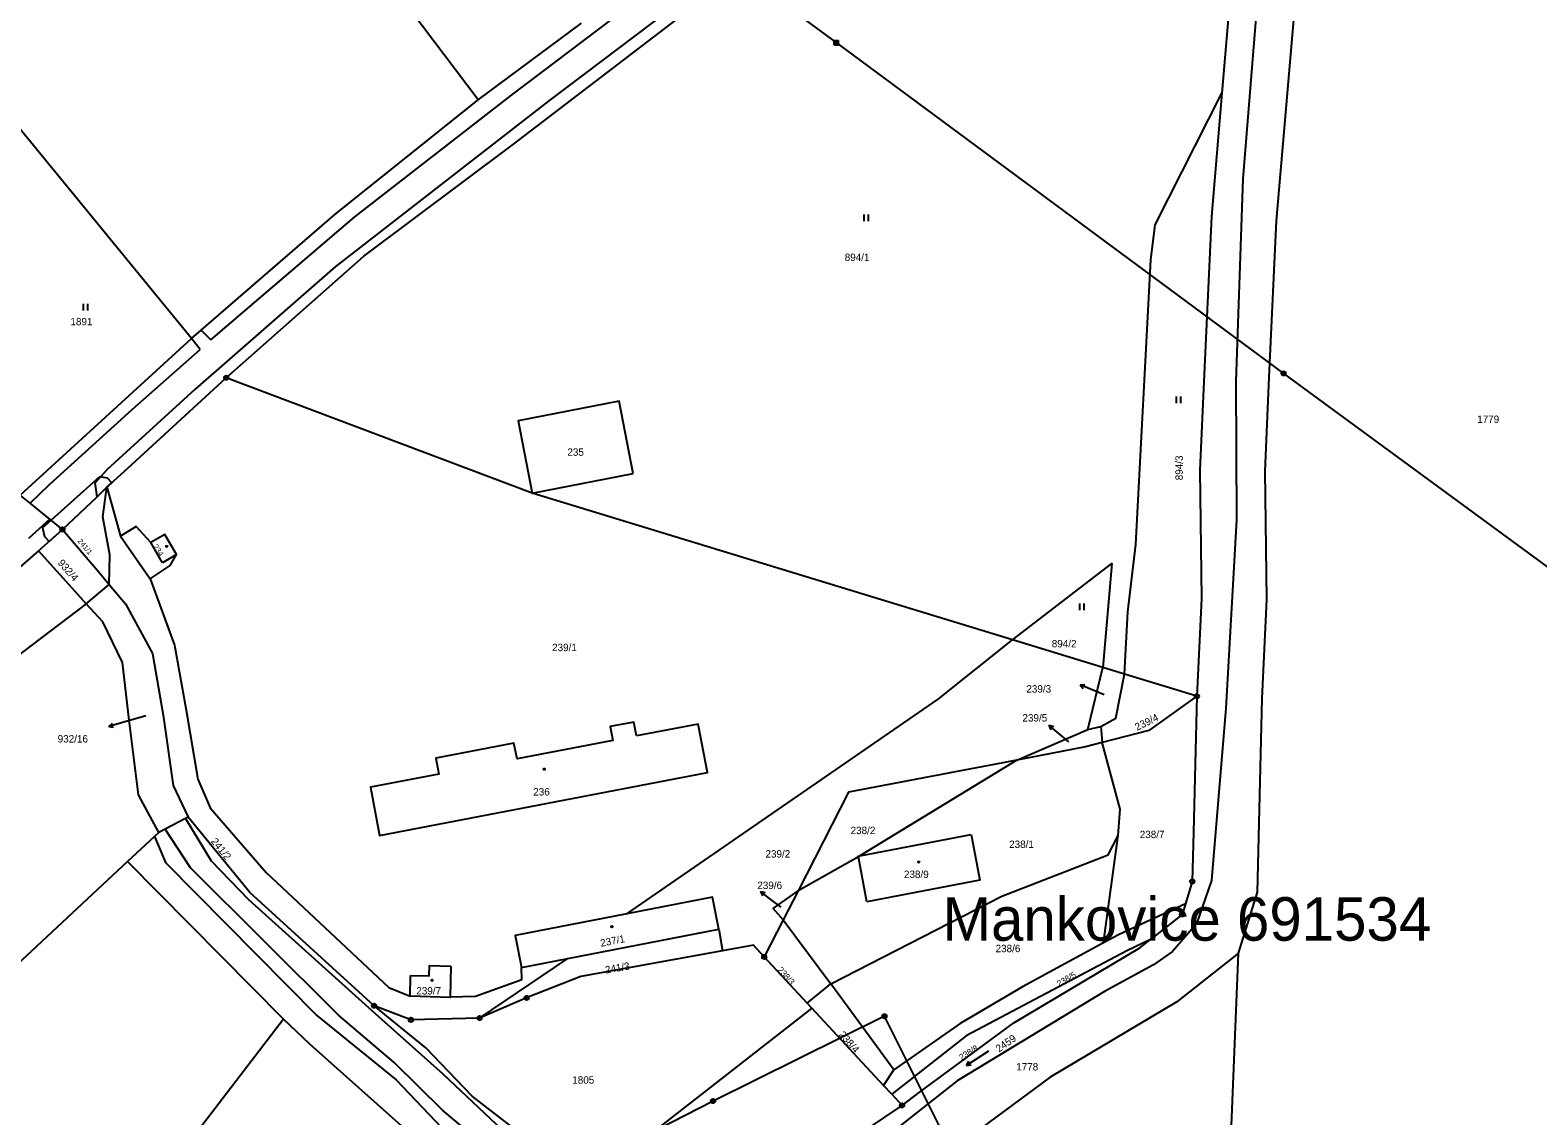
# Model space of a CAD drawing. Extents: x -504988 to -494607, y -1123820 to -1114018.
# Drawn here: x -501232.9 to -500886.6, y -1120834.1 to -1120584.6 of the extents above; entities that cross this region are included whole.
import ezdxf

# ---------------------------------------------------------------- set-up
doc = ezdxf.new("R2010")
doc.units = 0
for name, color, linetype in [('Hranice parcel', 7, 'Continuous'), ('Parcelní čísla', 7, 'Continuous'), ('Pop  PČ popisy', 7, 'Continuous'), ('Poz předměty', 7, 'Continuous'), ('Vnitřní kresba', 7, 'Continuous'), ('Věcná břemena k části', 7, 'Continuous'), ('Značky bodu BP', 7, 'Continuous'), ('Značky budov', 7, 'Continuous'), ('Značky kultur', 7, 'Continuous')]:
    doc.layers.add(name, color=color, linetype=linetype)

msp = doc.modelspace()

# ---------------------------------------------------------------- linework, layer by layer
at = {"layer": 'Hranice parcel'}
for p, q in [((-501130, -1120600.61), (-501186.29, -1120526.21)), ((-501130, -1120600.61), (-501106.28, -1120583.04)), ((-501235.2, -1120691.45), (-501195.89, -1120655.5)), ((-501215.28, -1120689.67), (-501212.14, -1120700.88)), ((-501230.98, -1120704.27), (-501225.49, -1120699.35)), ((-501212.14, -1120700.88), (-501205.36, -1120710.72)), ((-501220.02, -1120716.41), (-501214.75, -1120712.02)), ((-501220.02, -1120716.41), (-501366.55, -1120827.4)), ((-500986.5, -1120731.07), (-501007.24, -1120724.73)), ((-500989.97, -1120745.29), (-500986.5, -1120731.07)), ((-500981.55, -1120732.58), (-500986.5, -1120731.07)), ((-500964.91, -1120737.67), (-500981.55, -1120732.58)), ((-500989.97, -1120745.29), (-500986.94, -1120744.63)), ((-500986.94, -1120744.63), (-500986.67, -1120748.33)), ((-501006.25, -1120752.34), (-500989.97, -1120745.29)), ((-501006.25, -1120752.34), (-501042.29, -1120774.34)), ((-501196.61, -1120765.46), (-501197.25, -1120765.8)), ((-501203.37, -1120768.99), (-501204.37, -1120769.92)), ((-501201.9, -1120768.22), (-501203.37, -1120768.99)), ((-501197.25, -1120765.8), (-501201.9, -1120768.22)), ((-501204.37, -1120769.92), (-501210.52, -1120775.64)), ((-501042.29, -1120774.34), (-501016.74, -1120769.45)), ((-500986.36, -1120794.35), (-500983, -1120769.64)), ((-501210.52, -1120775.64), (-501314.36, -1120872.14)), ((-501174.71, -1120811.84), (-501210.52, -1120775.64)), ((-501042.67, -1120774.56), (-501056.51, -1120782.35)), ((-501040.7, -1120784.89), (-501042.67, -1120774.56)), ((-501056.51, -1120782.35), (-501059.92, -1120789.02)), ((-501059.92, -1120789.02), (-501064.3, -1120797.57)), ((-501059.92, -1120789.02), (-501049, -1120803.74)), ((-501109.41, -1120797.95), (-501074.74, -1120791.19)), ((-501074.74, -1120791.19), (-501073.87, -1120796.18)), ((-500959.49, -1120899.46), (-500955.35, -1120796.7)), ((-501136.26, -1120799.7), (-501136.44, -1120806.74)), ((-501129.67, -1120811.62), (-501109.41, -1120797.95)), ((-501120.03, -1120800.02), (-501109.41, -1120797.95)), ((-501054.46, -1120808.17), (-501064.3, -1120797.57)), ((-501145.66, -1120806.61), (-501145.55, -1120801.81)), ((-501054.46, -1120808.17), (-501049, -1120803.74)), ((-501034.53, -1120823.54), (-501049, -1120803.74)), ((-501053.37, -1120809.34), (-501105.86, -1120850.26)), ((-501053.37, -1120809.34), (-501054.46, -1120808.17)), ((-501036.9, -1120827.08), (-501053.37, -1120809.34)), ((-501174.71, -1120811.84), (-501240.43, -1120897.51)), ((-501036.9, -1120827.08), (-501034.53, -1120823.54)), ((-501035, -1120829.12), (-501036.9, -1120827.08)), ((-501035, -1120829.12), (-501032.63, -1120831.67))]:
    msp.add_line(p, q, dxfattribs=at)
for points in [[(-500953.35, -1120500.48), (-500952.09, -1120504.18), (-500951.44, -1120512.93), (-500952.93, -1120529.76), (-500954.82, -1120550.96), (-500957.14, -1120574.84), (-500959.18, -1120599.12)], [(-500947.89, -1120547.6), (-500950.64, -1120573.28), (-500954.32, -1120618.75), (-500955.93, -1120665.39), (-500955.81, -1120697.13), (-500958.29, -1120740.41), (-500961.53, -1120780.04), (-500965, -1120789.98), (-500970.48, -1120796.33), (-500974.88, -1120799.38), (-500986.12, -1120805.48), (-501019.95, -1120826.04), (-501047.16, -1120847.46), (-501062.53, -1120859.4), (-501071.7, -1120870.74), (-501073.06, -1120874.33), (-501072.36, -1120882.36)], [(-500955.35, -1120796.7), (-500951.01, -1120782.68), (-500949.92, -1120738.22), (-500948.81, -1120715.48), (-500949.25, -1120685.97), (-500948.28, -1120664.36), (-500946.58, -1120628.41), (-500941.57, -1120569.67), (-500939.6, -1120548.48)], [(-501187.87, -1120664.49), (-501156.29, -1120636.52), (-501121.86, -1120610.86), (-501053.65, -1120558.6), (-501052.27, -1120557.56), (-501048.06, -1120554.37)], [(-501195.89, -1120655.5), (-501252.94, -1120585.81), (-501254.29, -1120586.94)], [(-500981.55, -1120732.58), (-500980.8, -1120718.25), (-500978.95, -1120702.84), (-500975.46, -1120637.37), (-500974.45, -1120629.33), (-500959.18, -1120599.12)], [(-500959.18, -1120599.12), (-500961.55, -1120627.43), (-500963.26, -1120663.67), (-500964.26, -1120685.74), (-500963.82, -1120715.23), (-500964.91, -1120737.67)], [(-501195.89, -1120655.5), (-501193.62, -1120653.54), (-501163.04, -1120627.08), (-501130, -1120600.61)], [(-501215.28, -1120689.67), (-501210.5, -1120685.27), (-501187.87, -1120664.49)], [(-501007.24, -1120724.73), (-501117.61, -1120691), (-501187.87, -1120664.49)], [(-501094.41, -1120686.47), (-501097.65, -1120669.88), (-501120.84, -1120674.41), (-501117.61, -1120691), (-501094.41, -1120686.47)], [(-501225.49, -1120699.35), (-501228.4, -1120696.98), (-501232.93, -1120693.3), (-501235.2, -1120691.45)], [(-501225.49, -1120699.35), (-501217.56, -1120691.83), (-501215.28, -1120689.67)], [(-501214.75, -1120712.02), (-501214.62, -1120705.15), (-501216.24, -1120696.42), (-501215.28, -1120689.67)], [(-501225.49, -1120699.35), (-501217.33, -1120708.97), (-501214.75, -1120712.02)], [(-501205.36, -1120710.72), (-501200.74, -1120707.63), (-501199.26, -1120705.12), (-501201.96, -1120700.48), (-501205.21, -1120702.36), (-501208.58, -1120698.66), (-501212.14, -1120700.88)], [(-501230.98, -1120704.27), (-501252.35, -1120722.85), (-501305.53, -1120771.37), (-501366.55, -1120827.4)], [(-501220.02, -1120716.41), (-501222.57, -1120713.59), (-501230.98, -1120704.27)], [(-501007.24, -1120724.73), (-500984.47, -1120707.2), (-500986.5, -1120731.07)], [(-501214.75, -1120712.02), (-501211, -1120716.45), (-501204.81, -1120727.86), (-501202.33, -1120742.03), (-501200.04, -1120758.21), (-501196.61, -1120765.46)], [(-501205.36, -1120710.72), (-501199.78, -1120725.91), (-501197.05, -1120740.84), (-501194.38, -1120756.72), (-501191.54, -1120763.33), (-501178.69, -1120778.14), (-501150.56, -1120804.61), (-501145.66, -1120806.61)], [(-501203.37, -1120768.99), (-501208.01, -1120760.34), (-501210.19, -1120743.14), (-501211.74, -1120729.94), (-501216.22, -1120720.61), (-501220.02, -1120716.41)], [(-501095.84, -1120787.63), (-501024.32, -1120738.34), (-501007.24, -1120724.73)], [(-500986.94, -1120744.63), (-500983.51, -1120742.68), (-500981.55, -1120732.58)], [(-500964.91, -1120737.67), (-500975.93, -1120745.52), (-500986.67, -1120748.33)], [(-500964.91, -1120737.67), (-500965.67, -1120768.89), (-500965.95, -1120780.23), (-500967.54, -1120785.34)], [(-501093.61, -1120746.8), (-501094.22, -1120743.61), (-501099.65, -1120744.62), (-501099.03, -1120747.84), (-501121.08, -1120752.08), (-501121.78, -1120748.45), (-501139.75, -1120751.91), (-501139.05, -1120755.54), (-501154.76, -1120758.57), (-501152.63, -1120769.66), (-501077.3, -1120755.17), (-501079.43, -1120744.07), (-501093.61, -1120746.8)], [(-500986.67, -1120748.33), (-500990.47, -1120749.33), (-501006.25, -1120752.34)], [(-500983, -1120769.64), (-500982.54, -1120763.63), (-500986.67, -1120748.33)], [(-501006.25, -1120752.34), (-501044.92, -1120759.73), (-501056.51, -1120782.35)], [(-501153.91, -1120808.77), (-501182.43, -1120782.74), (-501196.61, -1120765.46)], [(-501046.7, -1120951.7), (-501049.76, -1120930.89), (-501064.68, -1120897.65), (-501079.51, -1120883.82), (-501096.53, -1120870.39), (-501115.41, -1120851.92), (-501138.23, -1120832.75), (-501149.31, -1120821.85), (-501162.09, -1120810.95), (-501196.12, -1120777.08), (-501201.9, -1120768.22)], [(-501197.25, -1120765.8), (-501191.36, -1120775.48), (-501182.76, -1120784.36), (-501152.9, -1120811.26), (-501138.08, -1120824.43), (-501123.11, -1120838.57), (-501110.83, -1120850.18), (-501100.06, -1120859.64), (-501084.74, -1120871.11), (-501076.33, -1120879)], [(-501204.37, -1120769.92), (-501201.85, -1120775.87), (-501167.05, -1120811.05), (-501148.8, -1120825.79), (-501138.33, -1120836.82), (-501117.04, -1120855.26), (-501098.03, -1120873.19), (-501091.8, -1120877.35), (-501089.38, -1120879.29), (-501082.27, -1120886.18), (-501066.39, -1120898.56), (-501051.55, -1120929.97), (-501051.19, -1120935.29), (-501048.87, -1120953.86), (-501041.61, -1120973.69), (-501040.41, -1120978.52), (-501040.21, -1120982.32), (-501040.6, -1120985.9), (-501041.96, -1120990.46), (-501043.41, -1120993.34), (-501047.71, -1121000.62)], [(-501049, -1120803.74), (-501009.68, -1120783.6), (-500985.25, -1120774.14), (-500983, -1120769.64)], [(-501016.74, -1120769.45), (-501014.74, -1120779.94), (-501040.7, -1120784.89)], [(-501042.67, -1120774.56), (-501042.69, -1120774.41), (-501042.29, -1120774.34)], [(-501059.92, -1120789.02), (-501062.22, -1120786.47), (-501056.51, -1120782.35)], [(-501074.74, -1120791.19), (-501076.18, -1120783.8), (-501095.84, -1120787.63)], [(-500967.54, -1120785.34), (-500982.93, -1120792.48), (-500986.36, -1120794.35)], [(-500967.54, -1120785.34), (-500968.3, -1120787.81), (-500975.55, -1120793.54)], [(-501095.84, -1120787.63), (-501121.47, -1120792.63), (-501120.03, -1120800.02)], [(-501073.87, -1120796.18), (-501106.45, -1120802.06), (-501118.87, -1120806.98), (-501129.67, -1120811.62)], [(-501064.3, -1120797.57), (-501066.78, -1120794.9), (-501073.87, -1120796.18)], [(-500955.35, -1120796.7), (-500969.5, -1120807.87), (-500998.63, -1120825.2), (-501019.77, -1120840.79), (-501071.05, -1120883.47)], [(-500975.55, -1120793.54), (-500981.01, -1120796.17), (-501017.88, -1120815.67), (-501035, -1120829.12)], [(-500986.36, -1120794.35), (-501004.94, -1120804.45), (-501019.25, -1120812.85), (-501034.53, -1120823.54)], [(-501032.63, -1120831.67), (-501028.71, -1120828.74), (-501006.93, -1120812.69), (-500978.02, -1120795.49), (-500975.55, -1120793.54)], [(-501145.55, -1120801.81), (-501141.26, -1120801.93), (-501141.2, -1120799.56), (-501136.26, -1120799.7)], [(-501136.44, -1120806.74), (-501130.58, -1120806.56), (-501119.97, -1120802.75), (-501120.03, -1120800.02)], [(-501136.44, -1120806.74), (-501136.44, -1120806.9), (-501145.66, -1120806.61)], [(-501105.86, -1120850.26), (-501113.83, -1120843.12), (-501131.41, -1120829.58), (-501142, -1120818.43), (-501153.91, -1120808.77)], [(-501129.67, -1120811.62), (-501145.46, -1120812.02), (-501153.91, -1120808.77)], [(-501114.57, -1120865.85), (-501168.67, -1120817.63), (-501174.71, -1120811.84)], [(-501080.17, -1120873.27), (-501077.62, -1120868.06), (-501070.91, -1120860.89), (-501057.97, -1120850.7), (-501040.78, -1120837.21), (-501032.63, -1120831.67)]]:
    msp.add_lwpolyline(points, dxfattribs=at)
at = {"layer": 'Pop  PČ popisy'}
for p, q in [((-500991.73, -1120735.04), (-500990.61, -1120734.97)), ((-500988.97, -1120736.21), (-500991.73, -1120735.04)), ((-500991.73, -1120735.04), (-500991.01, -1120735.89)), ((-500986.21, -1120737.37), (-500988.97, -1120736.21)), ((-501211.97, -1120743.78), (-501214.85, -1120744.61)), ((-501214.85, -1120744.61), (-501214.03, -1120743.85)), ((-501214.85, -1120744.61), (-501213.75, -1120744.81)), ((-501206.35, -1120742.14), (-501211.97, -1120743.78)), ((-500996.59, -1120746.26), (-500998.89, -1120744.33)), ((-500998.89, -1120744.33), (-500997.8, -1120744.59)), ((-500998.89, -1120744.33), (-500998.44, -1120745.36)), ((-500994.29, -1120748.18), (-500996.59, -1120746.26)), ((-501062.78, -1120784.34), (-501065.18, -1120782.53)), ((-501065.18, -1120782.53), (-501064.08, -1120782.74)), ((-501065.18, -1120782.53), (-501064.68, -1120783.54)), ((-501060.38, -1120786.14), (-501062.78, -1120784.34))]:
    msp.add_line(p, q, dxfattribs=at)
at = {"layer": 'Poz předměty'}
for p, q in [((-501198.35, -1120476.45), (-501047.72, -1120587.51)), ((-501048.22, -1120587.01), (-501047.22, -1120587.01)), ((-501048.22, -1120588.01), (-501048.22, -1120587.01)), ((-501048.22, -1120587.21), (-501047.22, -1120587.21)), ((-501048.22, -1120587.41), (-501047.22, -1120587.41)), ((-501048.22, -1120587.61), (-501047.22, -1120587.61)), ((-501048.22, -1120587.81), (-501047.22, -1120587.81)), ((-501048.22, -1120588.01), (-501047.22, -1120588.01)), ((-501048.02, -1120588.01), (-501048.02, -1120587.01)), ((-501047.82, -1120588.01), (-501047.82, -1120587.01)), ((-501047.72, -1120587.51), (-500944.98, -1120663.51)), ((-501047.62, -1120588.01), (-501047.62, -1120587.01)), ((-501047.42, -1120588.01), (-501047.42, -1120587.01)), ((-501047.22, -1120588.01), (-501047.22, -1120587.01)), ((-500944.98, -1120663.51), (-500835.5, -1120743.91)), ((-501036.67, -1120811.2), (-501076.03, -1120830.68)), ((-501019.45, -1120845.49), (-501036.67, -1120811.2)), ((-501076.03, -1120830.68), (-501110.07, -1120848.14))]:
    msp.add_line(p, q, dxfattribs=at)
for centre, radius in [((-500944.98, -1120663.51), 0.5), ((-500944.98, -1120663.51), 0.4), ((-500944.98, -1120663.51), 0.3), ((-500944.98, -1120663.51), 0.2), ((-500944.98, -1120663.51), 0.1), ((-501036.67, -1120811.2), 0.5), ((-501036.67, -1120811.2), 0.4), ((-501036.67, -1120811.2), 0.3), ((-501036.67, -1120811.2), 0.2), ((-501036.67, -1120811.2), 0.1), ((-501076.03, -1120830.68), 0.5), ((-501076.03, -1120830.68), 0.4), ((-501076.03, -1120830.68), 0.3), ((-501076.03, -1120830.68), 0.2), ((-501076.03, -1120830.68), 0.1)]:
    msp.add_circle(centre, radius, dxfattribs=at)
at = {"layer": 'Vnitřní kresba'}
for p, q in [((-501122.32, -1120599.55), (-501060.8, -1120553.01)), ((-501054.51, -1120556.07), (-501113.76, -1120600.89)), ((-501113.76, -1120600.89), (-501162.85, -1120639.01)), ((-501158.35, -1120627.55), (-501122.32, -1120599.55)), ((-501191.4, -1120655.75), (-501158.35, -1120627.55)), ((-501162.85, -1120639.01), (-501195, -1120667.1)), ((-501191.4, -1120655.75), (-501193.62, -1120653.54)), ((-501209.52, -1120671.8), (-501193.85, -1120658.03)), ((-501193.85, -1120658.03), (-501195.89, -1120655.5)), ((-501195, -1120667.1), (-501215.26, -1120685.61)), ((-501228.47, -1120689), (-501209.52, -1120671.8)), ((-501215.26, -1120685.61), (-501217.97, -1120688.6)), ((-501232.93, -1120693.3), (-501228.47, -1120689)), ((-501217.56, -1120691.83), (-501217.97, -1120688.6)), ((-501228.4, -1120696.98), (-501233.33, -1120701.42)), ((-501202.52, -1120707.01), (-501205.21, -1120702.36)), ((-501199.26, -1120705.12), (-501202.52, -1120707.01))]:
    msp.add_line(p, q, dxfattribs=at)
at = {"layer": 'Věcná břemena k části'}
msp.add_lwpolyline([(-501228.09, -1120697.23), (-501230.05, -1120699.01), (-501229.59, -1120700.98), (-501228.58, -1120702.12), (-501225.49, -1120699.35), (-501217.56, -1120691.83), (-501215.28, -1120689.67), (-501214.16, -1120688.64), (-501215.18, -1120687.54), (-501217.01, -1120687.24)], close=True, dxfattribs=at)
at = {"layer": 'Značky bodu BP'}
for centre, radius in [((-501187.87, -1120664.49), 0.5), ((-501187.87, -1120664.49), 0.0303), ((-501225.49, -1120699.35), 0.5), ((-501225.49, -1120699.35), 0.0303), ((-500964.91, -1120737.67), 0.5), ((-500964.91, -1120737.67), 0.0303), ((-500965.95, -1120780.23), 0.5), ((-500965.95, -1120780.23), 0.0303), ((-500968.3, -1120787.81), 0.5), ((-500968.3, -1120787.81), 0.0303), ((-501064.3, -1120797.57), 0.5), ((-501064.3, -1120797.57), 0.0303), ((-501118.87, -1120806.98), 0.5), ((-501118.87, -1120806.98), 0.0303), ((-501153.91, -1120808.77), 0.5), ((-501153.91, -1120808.77), 0.0303), ((-501145.46, -1120812.02), 0.5), ((-501145.46, -1120812.02), 0.0303), ((-501129.67, -1120811.62), 0.5), ((-501129.67, -1120811.62), 0.0303), ((-501032.63, -1120831.67), 0.5), ((-501032.63, -1120831.67), 0.0303)]:
    msp.add_circle(centre, radius, dxfattribs=at)
at = {"layer": 'Značky budov'}
for centre in [(-501201.54, -1120703.25), (-501114.83, -1120754.43), (-501028.79, -1120775.78), (-501099.29, -1120790.61), (-501140.58, -1120802.95)]:
    msp.add_circle(centre, 0.175, dxfattribs=at)
at = {"layer": 'Značky kultur'}
for p, q in [((-501041.37, -1120628.52), (-501041.37, -1120627.02)), ((-501040.37, -1120628.52), (-501040.37, -1120627.02)), ((-501220.67, -1120649.02), (-501220.67, -1120647.52)), ((-501219.67, -1120649.02), (-501219.67, -1120647.52)), ((-500969.59, -1120670.3), (-500969.59, -1120668.8)), ((-500968.59, -1120670.3), (-500968.59, -1120668.8)), ((-500991.79, -1120717.87), (-500991.79, -1120716.37)), ((-500990.79, -1120717.87), (-500990.79, -1120716.37)), ((-501012.8, -1120819.24), (-501017.84, -1120822.51)), ((-501017.84, -1120822.51), (-501017.29, -1120821.55)), ((-501017.84, -1120822.51), (-501016.74, -1120822.39))]:
    msp.add_line(p, q, dxfattribs=at)

# ---------------------------------------------------------------- texts
at = {"layer": 'Parcelní čísla'}
for s, p in [('894/1', (-501045.8, -1120637.66)), ('1891', (-501223.66, -1120652.44)), ('1779', (-500900.52, -1120674.88)), ('235', (-501109.51, -1120682.42)), ('239/1', (-501113.02, -1120727.31)), ('894/2', (-500998.24, -1120726.44)), ('239/3', (-501004.07, -1120736.83)), ('239/5', (-501004.97, -1120743.48)), ('932/16', (-501226.59, -1120748.3)), ('236', (-501117.35, -1120760.48)), ('238/2', (-501044.45, -1120769.35)), ('238/7', (-500978.03, -1120770.27)), ('238/1', (-501008.03, -1120772.53)), ('239/2', (-501064, -1120774.74)), ('238/9', (-501032.19, -1120779.43)), ('239/6', (-501065.88, -1120781.97)), ('238/6', (-501011.14, -1120796.48)), ('239/7', (-501144.21, -1120806.2)), ('1778', (-501006.41, -1120823.66)), ('1805', (-501108.39, -1120826.69))]:
    msp.add_text(s, height=1.7, dxfattribs=at).set_placement(p)
for s, height, rotation, p in [('894/3', 1.7, 90, (-500968.14, -1120688.05)), ('241/1', 1.2, 310, (-501222.09, -1120702.11)), ('234', 1.307, 304, (-501204.82, -1120703.28)), ('932/4', 1.7, 311, (-501226.68, -1120707.12)), ('239/4', 1.7, 26, (-500978.65, -1120745.63)), ('241/2', 1.7, 309, (-501191.48, -1120771.08)), ('237/1', 1.7, 11, (-501101.77, -1120795.25)), ('241/3', 1.7, 10, (-501100.68, -1120801.42)), ('238/3', 1.4, 312, (-501061.33, -1120800.63)), ('238/5', 1.4, 30, (-500996.56, -1120804.43)), ('238/4', 1.7, 311, (-501047.28, -1120815.52)), ('2459', 1.7, 35, (-501010.37, -1120819.56)), ('238/8', 1.4, 32, (-501018.96, -1120821.37))]:
    msp.add_text(s, height=height, rotation=rotation, dxfattribs=at).set_placement(p)
at = {"layer": 'Pop  PČ popisy'}
msp.add_text('Mankovice 691534', height=10, dxfattribs=at).set_placement((-501023.33, -1120793.84))

doc.saveas('drawing.dxf')
